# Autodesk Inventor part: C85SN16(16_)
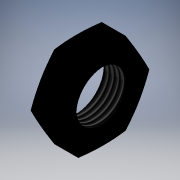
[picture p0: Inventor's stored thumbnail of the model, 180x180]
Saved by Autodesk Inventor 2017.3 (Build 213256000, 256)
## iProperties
Part Number: C85SN16(16_)
Material: Generic
Catalog Web Link: www.cadenas.de
Description: C85/CD85 MOUNTING_NUT-ISO Standard Air Cylinder:Standard Type Double Acting Single Rod
Vendor: SMC
Document SubType Name: Modeling
Designer: partserver
Manufacturer: SMC
Mass: 2.64727 g
Surface Area: 16.331 cm^2
Volume: 2.64727 cm^3
Density: 1 g/cm^3
Appearance: PSOLRGB-0-0-0
Category: PARTsolutions
Company: SMC
Title: C85SN16
Author: Cadenas PARTsolutions
Comments: ISO Standard Air Cylinder:Standard Type Double Acting Single Rod
PSOL_IDENT_0: {$CADENAS_DATA\23d-libs\smc_jp\actuator\standard_air_cylinder\c85\c85\parts\c85_m_nut.prj},178 {VTYP=
PSOL_IDENT_1: 3D},{NB=C85SN16(16_)},{LINA=C85SN16},{NN=C85/CD85 MOUNTING_NUT},{DATE=09.12.2020 02:57:06},{GEOMDATE=
PSOL_IDENT_2: 28.04.2020 08:30:14},{VERSION=},{LINEID=40},{WBVAR=OMSC},{WBNUMERIC=}  {NB=C85SN16(16_)},{LINA=C85SN
PSOL_IDENT_3: 16},{KT=DUMMY},{MODEL=C85SN16},{BORE=16},{OMSC=},{BE=M16x1.5},{BED=16},{BEJ=1.500},{KV=24},{KW=8}
NB: C85SN16(16_)
NN: C85/CD85 MOUNTING_NUT
NT: ISO Standard Air Cylinder:Standard Type Double Acting Single Rod
NBSYN: $MODEL.($BORE._$OMSC.)
LINA: C85SN16
CATALOG: SMC (JP
BORE: 16
OMSC: (-) Without order
BE: M16x1.5
BED: 16
BEJ: 1.5
KV: 24
KW: 8
SUPPLIER: SMC
ARTICLENO: C85SN16(16_)
BOMINFO: C85SN16
CREATOR: CADENAS GmbH
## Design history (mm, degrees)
sketch "Sketch_1"
  geometry: L1 (8, 0)-(0, 0); L2 (0, 12)-(0, 8); L3 (0, 8)-(0.812, 7.188); L4 (0.812, 7.188)-(7.188, 7.188); L5 (7.188, 7.188)-(8, 8); L6 (8, 8)-(8, 12); L7 (8, 12)-(4, 26.928); L8 (4, 26.928)-(0, 12)
  constraints: 16 end point
revolve "Revolution1" sketch "Sketch_1" stored, may be unused: angle "d0" = 360 deg
thread "Thread1" dims "d1" = 6.376, "d2" = 0
sketch "Sketch_2"
  geometry: L1 (-6.928, 12)-(-13.856, 0); L2 (-13.856, 0)-(-6.928, -12); L3 (-6.928, -12)-(6.928, -12); L4 (6.928, -12)-(13.856, 0); L5 (13.856, 0)-(6.928, 12); L6 (6.928, 12)-(-6.928, 12); C1 r 36 at (0, 0); 1 further point
  constraints: 12 end point, 1 centre point
extrude "Extrusion1" cut sketch "Sketch_2" distance "d3" = 8; taper "d4" = 0 deg
node "MNUT_BODY_XY"
node "MNUT_BODY_YZ"
node "MNUT_BODY_ZX"
node "MNUT_BODY_X"
node "MNUT_BODY_Y"
node "MNUT_BODY_Z"
node "MNUT_BODY_Center"
body "Solid1"
